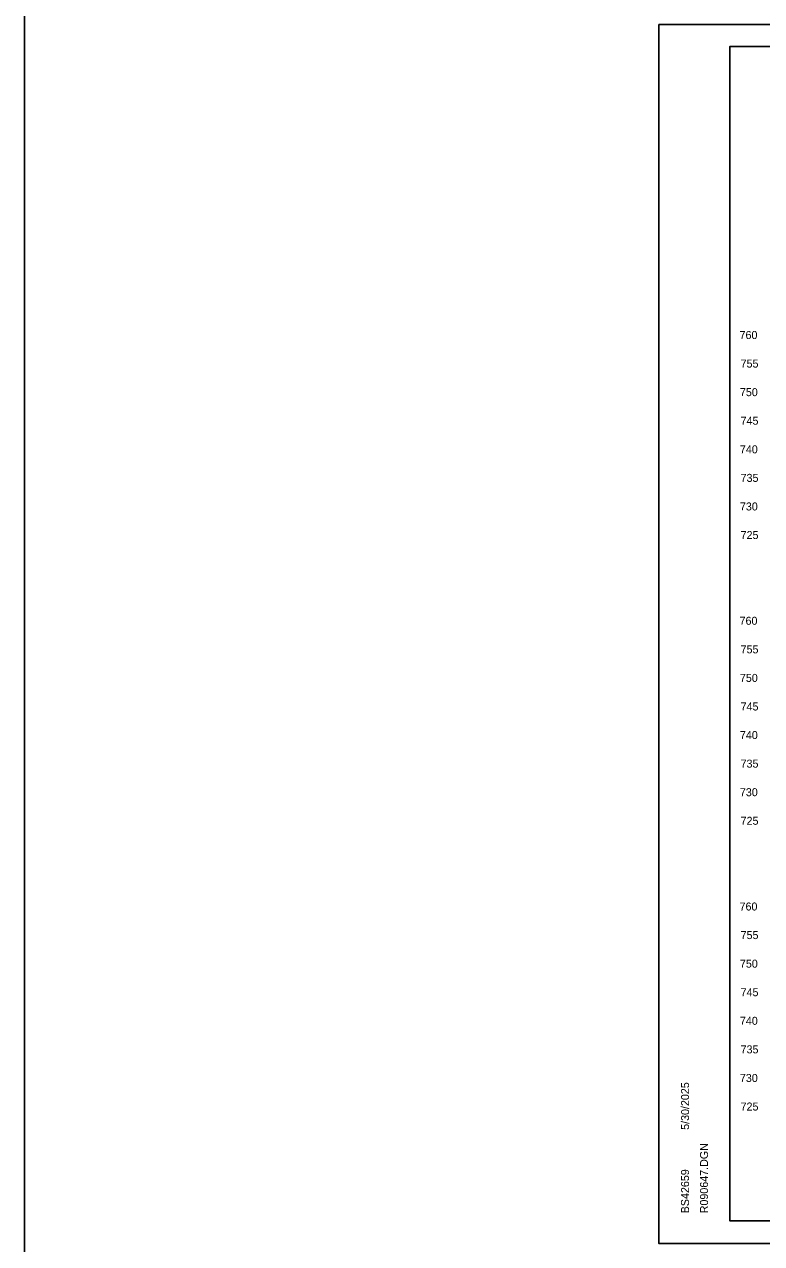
# Model space of a CAD drawing. Extents: x 1202951 to 1376887, y 378065 to 728038.
# Drawn here: x 1376303.2 to 1376432.2, y 378407.8 to 378621.2 of the extents above; entities that cross this region are included whole.
import ezdxf

# ---------------------------------------------------------------- set-up
doc = ezdxf.new("R2010")
doc.units = 0
for name, color, linetype in [('R_Axis Annot', 7, 'Continuous'), ('R_Border', 7, 'Continuous'), ('R_No Plot', 7, 'Continuous')]:
    doc.layers.add(name, color=color, linetype=linetype)

msp = doc.modelspace()

# ---------------------------------------------------------------- linework, layer by layer
at = {"layer": 'R_Border'}
for p, q in [((1376426.67, 378617.28), (1376742.85, 378617.28)), ((1376426.67, 378411.82), (1376426.67, 378617.28)), ((1376426.67, 378411.82), (1376426.67, 378411.82)), ((1376742.85, 378411.82), (1376426.67, 378411.82))]:
    msp.add_line(p, q, dxfattribs=at)
at = {"layer": 'R_No Plot'}
for p, q in [((1376414.27, 378621.17), (1376747.6, 378621.17)), ((1376414.27, 378407.84), (1376747.6, 378407.84))]:
    msp.add_line(p, q, dxfattribs=at)
for points in [[(1376303.24, 380162.87), (1376887.29, 380162.87), (1376887.29, 378065.39), (1376303.24, 378065.39)], [(1376414.26, 378621.17), (1376747.6, 378621.17), (1376747.6, 378407.83), (1376414.26, 378407.83)], [(1376660.59, 378617.28), (1376680.21, 378617.28), (1376680.21, 378607.4), (1376696.32, 378607.4), (1376719.52, 378607.4), (1376719.64, 378579.24), (1376742.85, 378579.24), (1376742.85, 378411.82), (1376426.67, 378411.82), (1376426.67, 378617.28)]]:
    msp.add_lwpolyline(points, close=True, dxfattribs=at)

# ---------------------------------------------------------------- texts
at = {"layer": 'R_Axis Annot'}
for s, p in [('760', (1376428.38, 378566.12)), ('755', (1376428.56, 378561.12)), ('750', (1376428.44, 378556.12)), ('745', (1376428.56, 378551.12)), ('740', (1376428.44, 378546.12)), ('735', (1376428.56, 378541.12)), ('730', (1376428.44, 378536.12)), ('725', (1376428.56, 378531.12)), ('760', (1376428.38, 378516.12)), ('755', (1376428.56, 378511.12)), ('750', (1376428.44, 378506.12)), ('745', (1376428.56, 378501.12)), ('740', (1376428.44, 378496.12)), ('735', (1376428.56, 378491.12)), ('730', (1376428.44, 378486.12)), ('725', (1376428.56, 378481.12)), ('760', (1376428.38, 378466.12)), ('755', (1376428.56, 378461.12)), ('750', (1376428.44, 378456.12)), ('745', (1376428.56, 378451.12)), ('740', (1376428.44, 378446.12)), ('735', (1376428.56, 378441.12)), ('730', (1376428.44, 378436.12)), ('725', (1376428.56, 378431.12))]:
    msp.add_text(s, height=1.4, dxfattribs=at).set_placement(p)
at = {"layer": 'R_Border'}
for s, p in [('5/30/2025', (1376419.54, 378427.74)), ('R090647.DGN', (1376422.86, 378413.14)), ('BS42659', (1376419.54, 378413.14))]:
    msp.add_text(s, height=1.4, rotation=90, dxfattribs=at).set_placement(p)

doc.saveas('drawing.dxf')
